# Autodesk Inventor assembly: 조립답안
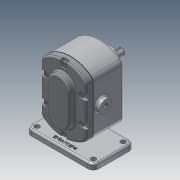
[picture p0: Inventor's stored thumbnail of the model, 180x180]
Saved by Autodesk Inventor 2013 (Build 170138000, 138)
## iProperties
Created: 2019-03
Part Number: 조립답안
Document SubType Name: Assembly
Designer: Administrator
Author: Administrator
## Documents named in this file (11)
- C:\Users\Administrator\Desktop\49030V1024\조립답안.iam
- C:\Users\Administrator\Desktop\49030V1024\본체.ipt
- C:\Users\Administrator\Desktop\49030V1024\개스킷.ipt
- C:\Users\Administrator\Desktop\49030V1024\메인축.ipt
- C:\Users\Administrator\Desktop\49030V1024\베어링부시.ipt
- C:\Users\Administrator\Desktop\49030V1024\볼트 M5.ipt
- C:\Users\Administrator\Desktop\49030V1024\서브축.ipt
- C:\Users\Administrator\Desktop\49030V1024\스퍼기어.ipt
- C:\Users\Administrator\Desktop\49030V1024\오일 실 16 28 7.ipt
- C:\Users\Administrator\Desktop\49030V1024\커버.ipt
- C:\Users\Administrator\Desktop\49030V1024\키 6 x 6 x 18.ipt
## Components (1 placed, 1 different names)
1. 개스킷:1
